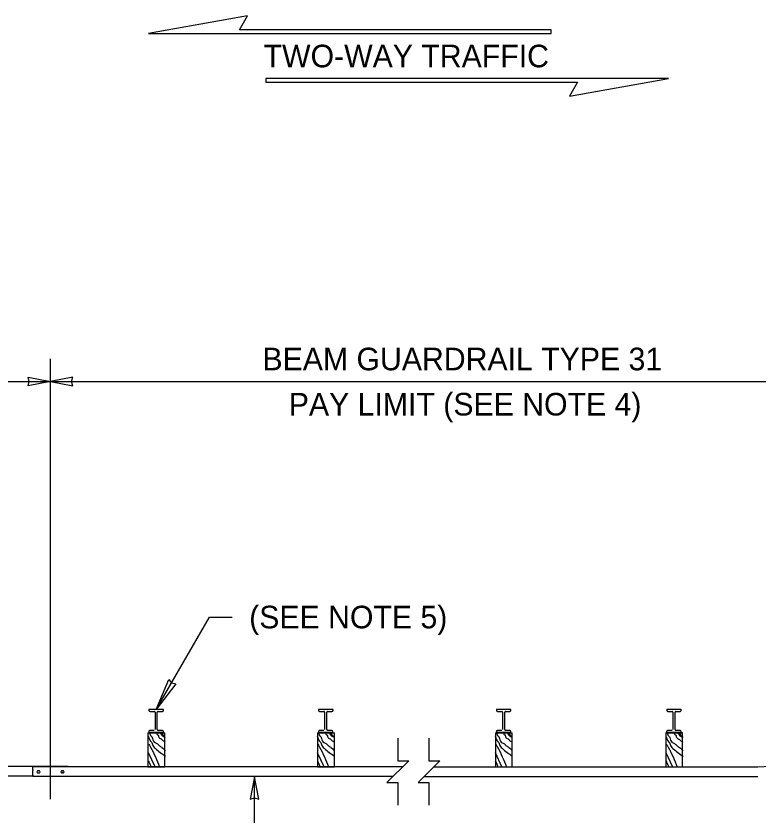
# Model space of a CAD drawing. Extents: x 99862 to 103680, y 99470 to 102076.
# Drawn here: x 100644 to 101170, y 100434 to 100999 of the extents above; entities that cross this region are included whole.
import ezdxf

# ---------------------------------------------------------------- set-up
doc = ezdxf.new("R2010")
doc.units = 0
for name, color, linetype in [('Level 10', 7, 'Continuous'), ('Level 13', 7, 'Continuous'), ('Level 15', 7, 'Continuous'), ('Level 2', 7, 'Continuous'), ('Level 20', 7, 'Continuous'), ('Level 3', 7, 'Continuous'), ('Level 4', 7, 'Continuous'), ('Level 9', 7, 'Continuous')]:
    doc.layers.add(name, color=color, linetype=linetype)

msp = doc.modelspace()

# ---------------------------------------------------------------- linework, layer by layer
at = {"layer": 'Level 10'}
for p, q in [((100737.55, 100492.08), (100737.55, 100468.08)), ((100737.55, 100492.08), (100749.55, 100492.08)), ((100749.55, 100468.08), (100749.55, 100492.08)), ((100857.55, 100492.08), (100869.55, 100492.08)), ((100857.55, 100492.08), (100857.55, 100468.08)), ((100869.55, 100468.08), (100869.55, 100492.08)), ((100983.55, 100492.08), (100995.55, 100492.08)), ((100983.55, 100492.08), (100983.55, 100468.08)), ((100995.55, 100468.08), (100995.55, 100492.08)), ((101116.15, 100492.08), (101104.15, 100492.08)), ((100737.55, 100468.08), (100749.55, 100468.08)), ((100742.61, 100468), (100742.61, 100468.08)), ((100742.96, 100468), (100742.96, 100468.08)), ((100742.96, 100468), (100742.96, 100468.08)), ((100744.49, 100468.08), (100744.49, 100468)), ((100744.84, 100468.08), (100744.84, 100468)), ((100744.84, 100468.08), (100744.84, 100468)), ((100857.55, 100468.08), (100869.55, 100468.08)), ((100862.61, 100468), (100862.61, 100468.08)), ((100862.61, 100468), (100862.61, 100468.08)), ((100864.49, 100468.08), (100864.49, 100468)), ((100864.49, 100468.08), (100864.49, 100468)), ((100983.55, 100468.08), (100995.55, 100468.08)), ((100988.58, 100468), (100988.58, 100468.08)), ((100988.58, 100468), (100988.58, 100468.08)), ((100990.46, 100468.08), (100990.46, 100468)), ((100990.46, 100468.08), (100990.46, 100468)), ((101109.48, 100467.92), (101109.48, 100468)), ((101109.48, 100467.92), (101109.48, 100468)), ((101111.35, 100468), (101111.35, 100467.92)), ((101111.35, 100468), (101111.35, 100467.92))]:
    msp.add_line(p, q, dxfattribs=at)
at = {"layer": 'Level 13'}
for p, q in [((100737.77, 100478.17), (100742.37, 100468.16)), ((100857.42, 100478.17), (100862.02, 100468.16)), ((100983.4, 100478.17), (100987.99, 100468.16)), ((101104.29, 100478.09), (101108.88, 100468.08))]:
    msp.add_line(p, q, dxfattribs=at)
for points in [[(100738.66, 100492.07), (100739.93, 100489.79), (100740.38, 100489.39), (100740.74, 100488), (100742.86, 100484.97), (100744.77, 100483.88), (100745.18, 100483.34), (100747.31, 100481.89), (100747.49, 100481.75), (100749.91, 100479.47)], [(100743.63, 100492.07), (100744.44, 100490.71), (100744.84, 100490.55), (100745.01, 100489.83), (100746.25, 100488.07), (100747.49, 100487.41), (100747.82, 100486.97), (100749.88, 100485.56)], [(100746.32, 100492.09), (100746.74, 100491.4), (100747.64, 100490.11), (100748.63, 100489.51), (100749.8, 100488.78)], [(100747.73, 100492.05), (100748.09, 100490.73), (100749.8, 100489.61)], [(100858.31, 100492.07), (100859.58, 100489.79), (100860.03, 100489.39), (100860.39, 100488), (100862.51, 100484.97), (100864.42, 100483.88), (100864.83, 100483.34), (100866.96, 100481.89), (100867.15, 100481.75), (100869.57, 100479.47)], [(100863.28, 100492.07), (100864.09, 100490.71), (100864.49, 100490.55), (100864.66, 100489.83), (100865.9, 100488.07), (100867.14, 100487.41), (100867.47, 100486.97), (100869.53, 100485.56)], [(100865.97, 100492.09), (100866.39, 100491.4), (100867.29, 100490.11), (100868.28, 100489.51), (100869.45, 100488.78)], [(100867.39, 100492.05), (100867.74, 100490.73), (100869.45, 100489.61)], [(100984.28, 100492.07), (100985.55, 100489.79), (100986, 100489.39), (100986.36, 100488), (100988.48, 100484.97), (100990.39, 100483.88), (100990.8, 100483.34), (100992.94, 100481.89), (100993.12, 100481.75), (100995.54, 100479.47)], [(100989.25, 100492.07), (100990.06, 100490.71), (100990.46, 100490.55), (100990.63, 100489.83), (100991.87, 100488.07), (100993.11, 100487.41), (100993.44, 100486.97), (100995.5, 100485.56)], [(100991.94, 100492.09), (100992.36, 100491.4), (100993.26, 100490.11), (100994.25, 100489.51), (100995.42, 100488.78)], [(100993.36, 100492.05), (100993.71, 100490.73), (100995.42, 100489.61)], [(101105.17, 100491.99), (101106.44, 100489.72), (101106.9, 100489.31), (101107.25, 100487.92), (101109.38, 100484.9), (101111.29, 100483.81), (101111.7, 100483.27), (101113.83, 100481.81), (101114.01, 100481.67), (101116.43, 100479.39)], [(101110.14, 100491.99), (101110.96, 100490.64), (101111.36, 100490.47), (101111.52, 100489.76), (101112.77, 100487.99), (101114, 100487.33), (101114.33, 100486.89), (101116.39, 100485.49)], [(101112.84, 100492.01), (101113.25, 100491.32), (101114.16, 100490.03), (101115.14, 100489.44), (101116.31, 100488.7)], [(101114.25, 100491.98), (101114.6, 100490.65), (101116.31, 100489.53)], [(100737.84, 100489.81), (100739.94, 100485.67), (100740.39, 100485.26), (100740.74, 100483.87), (100742.69, 100481.16), (100749.9, 100475.57)], [(100857.49, 100489.81), (100859.59, 100485.67), (100860.04, 100485.26), (100860.4, 100483.87), (100862.34, 100481.16), (100869.55, 100475.57)], [(100983.46, 100489.81), (100985.56, 100485.67), (100986.01, 100485.26), (100986.37, 100483.87), (100988.31, 100481.16), (100995.52, 100475.57)], [(101104.36, 100489.73), (101106.45, 100485.59), (101106.9, 100485.18), (101107.26, 100483.79), (101109.21, 100481.08), (101116.41, 100475.49)], [(100738.3, 100483.95), (100739.45, 100481.94), (100745.86, 100468.02)], [(100857.95, 100483.95), (100859.1, 100481.94), (100865.51, 100468.02)], [(100983.92, 100483.95), (100985.07, 100481.94), (100991.49, 100468.02)], [(101104.82, 100483.87), (101105.96, 100481.86), (101112.38, 100467.94)], [(100737.88, 100472.24), (100738.03, 100471.98), (100738.18, 100471.72), (100738.45, 100471.18), (100738.94, 100470.07), (100739.39, 100468.94), (100739.62, 100468.37), (100739.87, 100467.82)], [(100857.53, 100472.24), (100857.68, 100471.98), (100857.83, 100471.72), (100858.1, 100471.18), (100858.59, 100470.07), (100859.04, 100468.94), (100859.28, 100468.37), (100859.52, 100467.82)], [(100983.5, 100472.24), (100983.65, 100471.98), (100983.8, 100471.72), (100984.07, 100471.18), (100984.56, 100470.07), (100985.02, 100468.94), (100985.25, 100468.37), (100985.49, 100467.82)], [(101104.39, 100472.16), (101104.55, 100471.9), (101104.69, 100471.64), (101104.96, 100471.1), (101105.45, 100469.99), (101105.91, 100468.86), (101106.14, 100468.3), (101106.38, 100467.74)]]:
    msp.add_spline(points, degree=3, dxfattribs=at)
at = {"layer": 'Level 15'}
for p, q in [((100668.55, 100629.88), (100668.55, 100756.65)), ((100332.36, 100740.65), (100668.55, 100740.65)), ((100668.55, 100740.65), (101188.8, 100740.65)), ((100668.55, 100445.21), (100668.55, 100629.88)), ((100743.43, 100508.51), (100781.25, 100574.02)), ((100781.25, 100574.02), (100797.25, 100574.02)), ((100813.08, 100388.97), (100813.08, 100460.97))]:
    msp.add_line(p, q, dxfattribs=at)
for points in [[(100668.55, 100740.65), (100652.83, 100737.57), (100653.55, 100740.65), (100652.83, 100743.74)], [(100668.55, 100740.65), (100684.28, 100737.57), (100683.55, 100740.65), (100684.28, 100743.74)], [(100743.43, 100508.51), (100752.25, 100529.77), (100754.31, 100527.37), (100757.43, 100526.79)], [(100813.08, 100460.97), (100809.99, 100445.25), (100813.08, 100445.98), (100816.16, 100445.25)]]:
    msp.add_lwpolyline(points, close=True, dxfattribs=at)
for points in [[(100914.55, 100488.32), (100914.55, 100472.32), (100922.29, 100472.32), (100906.81, 100456.83), (100914.55, 100456.83), (100914.55, 100440.83)], [(100936.55, 100488.32), (100936.55, 100472.32), (100944.29, 100472.32), (100928.81, 100456.83), (100936.55, 100456.83), (100936.55, 100440.83)]]:
    msp.add_lwpolyline(points, dxfattribs=at)
at = {"layer": 'Level 2'}
for p, q in [((101169.31, 100468), (102001.12, 100508.71)), ((100681.05, 100468.25), (100599.55, 100468.25)), ((100656.05, 100467.95), (100656.05, 100467.96)), ((100656.05, 100465.93), (100656.05, 100467.95)), ((100917.93, 100467.95), (100656.05, 100467.95)), ((100656.05, 100465.93), (100656.05, 100465.54)), ((100656.05, 100462.12), (100656.05, 100465.54)), ((100660.27, 100465.19), (100659.83, 100465.19)), ((100659.83, 100463.7), (100660.27, 100463.7)), ((100675.93, 100464.44), (100675.93, 100464.52)), ((100676.83, 100465.19), (100677.27, 100465.19)), ((100677.27, 100463.7), (100676.83, 100463.7)), ((100678.18, 100464.52), (100678.18, 100464.44)), ((100681.05, 100467.95), (100681.05, 100468.25)), ((100917.97, 100468), (100681.05, 100468)), ((100939.97, 100468), (101066.49, 100468)), ((101066.49, 100468), (101169.31, 100468)), ((100656.05, 100461.45), (100381.03, 100461.45)), ((100656.05, 100462.12), (100656.05, 100461.2)), ((100911.18, 100461.2), (100656.05, 100461.2)), ((100933.18, 100461.2), (101044.49, 100461.2)), ((101044.49, 100461.2), (101169.45, 100461.2))]:
    msp.add_line(p, q, dxfattribs=at)
for centre, start_param, end_param in [((100659.83, 100464.44), 4.712389, 7.853982), ((100660.27, 100464.44), 1.570796, 4.712389), ((100676.83, 100464.44), 4.712389, 7.853982), ((100677.27, 100464.44), 1.570796, 4.712389)]:
    msp.add_ellipse(centre, major_axis=(-0.906, 0), ratio=0.823209, start_param=start_param, end_param=end_param, dxfattribs=at)
at = {"layer": 'Level 3'}
for points in [[(101023.06, 100989.54), (100802.32, 100989.54), (100808.02, 100999.4), (100738.05, 100987.07), (101023.06, 100987.07)], [(100821.05, 100952.59), (101041.78, 100952.59), (101036.09, 100942.74), (101106.05, 100955.07), (100821.05, 100955.07)]]:
    msp.add_lwpolyline(points, close=True, dxfattribs=at)
at = {"layer": 'Level 4'}
for p, q in [((101104.15, 100492.08), (101116.15, 100492.08)), ((101104.15, 100492.08), (101104.15, 100468.08)), ((101116.15, 100492.08), (101104.15, 100492.08)), ((101104.15, 100492.08), (101116.15, 100492.08)), ((101116.15, 100468.08), (101116.15, 100492.08)), ((101104.15, 100468.08), (101116.15, 100468.08))]:
    msp.add_line(p, q, dxfattribs=at)
at = {"layer": 'Level 9'}
for p, q in [((100742.65, 100506.65), (100742.64, 100500.51)), ((100744.19, 100500.51), (100744.19, 100506.65)), ((100862.65, 100506.65), (100862.64, 100500.51)), ((100864.19, 100500.51), (100864.19, 100506.65)), ((100988.65, 100506.65), (100988.64, 100500.51)), ((100990.19, 100500.51), (100990.19, 100506.65)), ((101109.25, 100506.65), (101109.24, 100500.51)), ((101110.78, 100500.51), (101110.79, 100506.65)), ((100742.64, 100500.51), (100742.64, 100494.37)), ((100744.18, 100494.37), (100744.19, 100500.51)), ((100862.64, 100500.51), (100862.64, 100494.37)), ((100864.18, 100494.37), (100864.19, 100500.51)), ((100988.64, 100500.51), (100988.64, 100494.37)), ((100990.18, 100494.37), (100990.19, 100500.51)), ((101109.24, 100500.51), (101109.23, 100494.37)), ((101110.78, 100494.37), (101110.78, 100500.51))]:
    msp.add_line(p, q, dxfattribs=at)
for points in [[(100743.43, 100508.51), (100738.26, 100508.52), (100738.26, 100508.03)], [(100739.04, 100507.24), (100742.06, 100507.24)], [(100748.59, 100508.02), (100748.6, 100508.5), (100743.43, 100508.51)], [(100744.79, 100507.24), (100747.81, 100507.23)], [(100863.43, 100508.51), (100858.26, 100508.52), (100858.26, 100508.03)], [(100859.04, 100507.24), (100862.06, 100507.24)], [(100868.59, 100508.02), (100868.6, 100508.5), (100863.43, 100508.51)], [(100864.79, 100507.24), (100867.81, 100507.23)], [(100989.43, 100508.51), (100984.26, 100508.52), (100984.26, 100508.03)], [(100985.04, 100507.24), (100988.06, 100507.24)], [(100994.59, 100508.02), (100994.6, 100508.5), (100989.43, 100508.51)], [(100990.79, 100507.24), (100993.81, 100507.23)], [(101110.02, 100508.51), (101104.85, 100508.52), (101104.85, 100508.03)], [(101105.64, 100507.24), (101108.66, 100507.24)], [(101115.19, 100508.02), (101115.19, 100508.5), (101110.02, 100508.51)], [(101111.38, 100507.24), (101114.4, 100507.23)], [(100738.24, 100493), (100738.24, 100492.52), (100743.41, 100492.51)], [(100742.04, 100493.78), (100739.03, 100493.79)], [(100743.41, 100492.51), (100748.57, 100492.5), (100748.58, 100492.99)], [(100747.79, 100493.78), (100744.77, 100493.78)], [(100858.24, 100493), (100858.24, 100492.52), (100863.41, 100492.51)], [(100862.04, 100493.78), (100859.03, 100493.79)], [(100863.41, 100492.51), (100868.57, 100492.5), (100868.58, 100492.99)], [(100867.79, 100493.78), (100864.77, 100493.78)], [(100984.24, 100493), (100984.24, 100492.52), (100989.41, 100492.51)], [(100988.04, 100493.78), (100985.03, 100493.79)], [(100989.41, 100492.51), (100994.57, 100492.5), (100994.58, 100492.99)], [(100993.79, 100493.78), (100990.77, 100493.78)], [(101104.83, 100493), (101104.83, 100492.52), (101110, 100492.51)], [(101108.64, 100493.78), (101105.62, 100493.79)], [(101110, 100492.51), (101115.17, 100492.5), (101115.17, 100492.99)], [(101114.39, 100493.78), (101111.37, 100493.78)]]:
    msp.add_lwpolyline(points, dxfattribs=at)
for centre, radius, start, end in [((100739.04, 100508.03), 0.788, 179.9273, 269.9273), ((100742.06, 100506.65), 0.591, 359.9273, 89.9273), ((100744.79, 100506.64), 0.591, 89.9273, 179.9273), ((100747.81, 100508.02), 0.788, 269.9273, 359.9273), ((100859.04, 100508.03), 0.788, 179.9273, 269.9273), ((100862.06, 100506.65), 0.591, 359.9273, 89.9273), ((100864.79, 100506.64), 0.591, 89.9273, 179.9273), ((100867.81, 100508.02), 0.788, 269.9273, 359.9273), ((100985.04, 100508.03), 0.788, 179.9273, 269.9273), ((100988.06, 100506.65), 0.591, 359.9273, 89.9273), ((100990.79, 100506.64), 0.591, 89.9273, 179.9273), ((100993.81, 100508.02), 0.788, 269.9273, 359.9273), ((101105.64, 100508.03), 0.788, 179.9273, 269.9273), ((101108.66, 100506.65), 0.591, 359.9273, 89.9273), ((101111.38, 100506.64), 0.591, 89.9273, 179.9273), ((101114.4, 100508.02), 0.788, 269.9273, 359.9273), ((100739.02, 100493), 0.788, 89.9273, 179.9478), ((100744.77, 100494.37), 0.591, 179.9273, 269.9273), ((100747.79, 100492.99), 0.788, 359.9478, 89.9273), ((100859.02, 100493), 0.788, 89.9273, 179.9478), ((100864.77, 100494.37), 0.591, 179.9273, 269.9273), ((100867.79, 100492.99), 0.788, 359.9478, 89.9273), ((100985.02, 100493), 0.788, 89.9273, 179.9478), ((100990.77, 100494.37), 0.591, 179.9273, 269.9273), ((100993.79, 100492.99), 0.788, 359.9478, 89.9273), ((101105.62, 100493), 0.788, 89.9273, 179.9478), ((101111.37, 100494.37), 0.591, 179.9273, 269.9273), ((101114.38, 100492.99), 0.788, 359.9478, 89.9273)]:
    msp.add_arc(centre, radius, start, end, dxfattribs=at)

# ---------------------------------------------------------------- texts
at = {"layer": 'Level 20'}
for s, p in [('TWO-WAY TRAFFIC', (100819.45, 100963.07)), ('BEAM GUARDRAIL TYPE 31 ', (100818.66, 100748.65)), (' PAY LIMIT (SEE NOTE 4)', (100831.35, 100716.65)), ('(SEE NOTE 5)', (100809.25, 100566.02))]:
    msp.add_text(s, height=16, dxfattribs=at).set_placement(p)

doc.saveas('drawing.dxf')
